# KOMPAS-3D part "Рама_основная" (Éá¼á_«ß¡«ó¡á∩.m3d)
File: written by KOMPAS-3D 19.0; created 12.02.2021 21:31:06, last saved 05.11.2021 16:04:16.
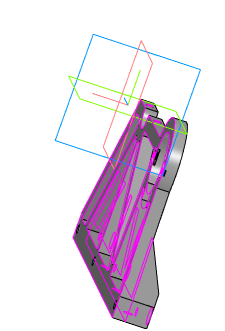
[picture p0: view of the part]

Document properties: Автор: Agent Smith; Полное имя файла: D:\3D_print\3D проекты Компас 3D\Халява Projects 5\Рама_основная.m3d

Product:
- Part/product: Рама_основная
    Масса: 0.415808

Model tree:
1. Эскиз:1  (with: Элемент выдавливания:1)
2. Элемент выдавливания:9
     Расстояние 2 = 6
3. Эскиз:9  (with: Элемент выдавливания:9)
4. Элемент выдавливания:11
     Расстояние 1 = 10
5. Уклон:3  (with: Элемент выдавливания:9, Элемент выдавливания:11)
     Угол уклона = -65
6. Эскиз:10  (with: Элемент выдавливания:9, Элемент выдавливания:11)
7. Элемент выдавливания:12  (with: Элемент выдавливания:9)
     Расстояние 2 = 10
8. Эскиз:11  (with: Элемент выдавливания:9)
9. Элемент выдавливания:13  (with: Элемент выдавливания:9)
     Расстояние 2 = 6.5
10. Эскиз:12  (with: Элемент выдавливания:9)
11. Элемент выдавливания:14
     Расстояние 2 = 1.2
12. Эскиз:13  (with: Элемент выдавливания:9, Элемент выдавливания:14)
13. Элемент выдавливания:15  (with: Элемент выдавливания:9)
     Расстояние 2 = 6
14. Эскиз:14  (with: Элемент выдавливания:11)
15. Элемент выдавливания:16
     Расстояние 2 = 6
16. Эскиз:15  (with: Элемент выдавливания:16)
17. Элемент выдавливания:17  (with: Элемент выдавливания:9)
     Расстояние 2 = 10

Referenced files in D:\3D_print\3D проекты Компас 3D\Редуктор (Снова)\: Намоточный станок (Projects 6).a3d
